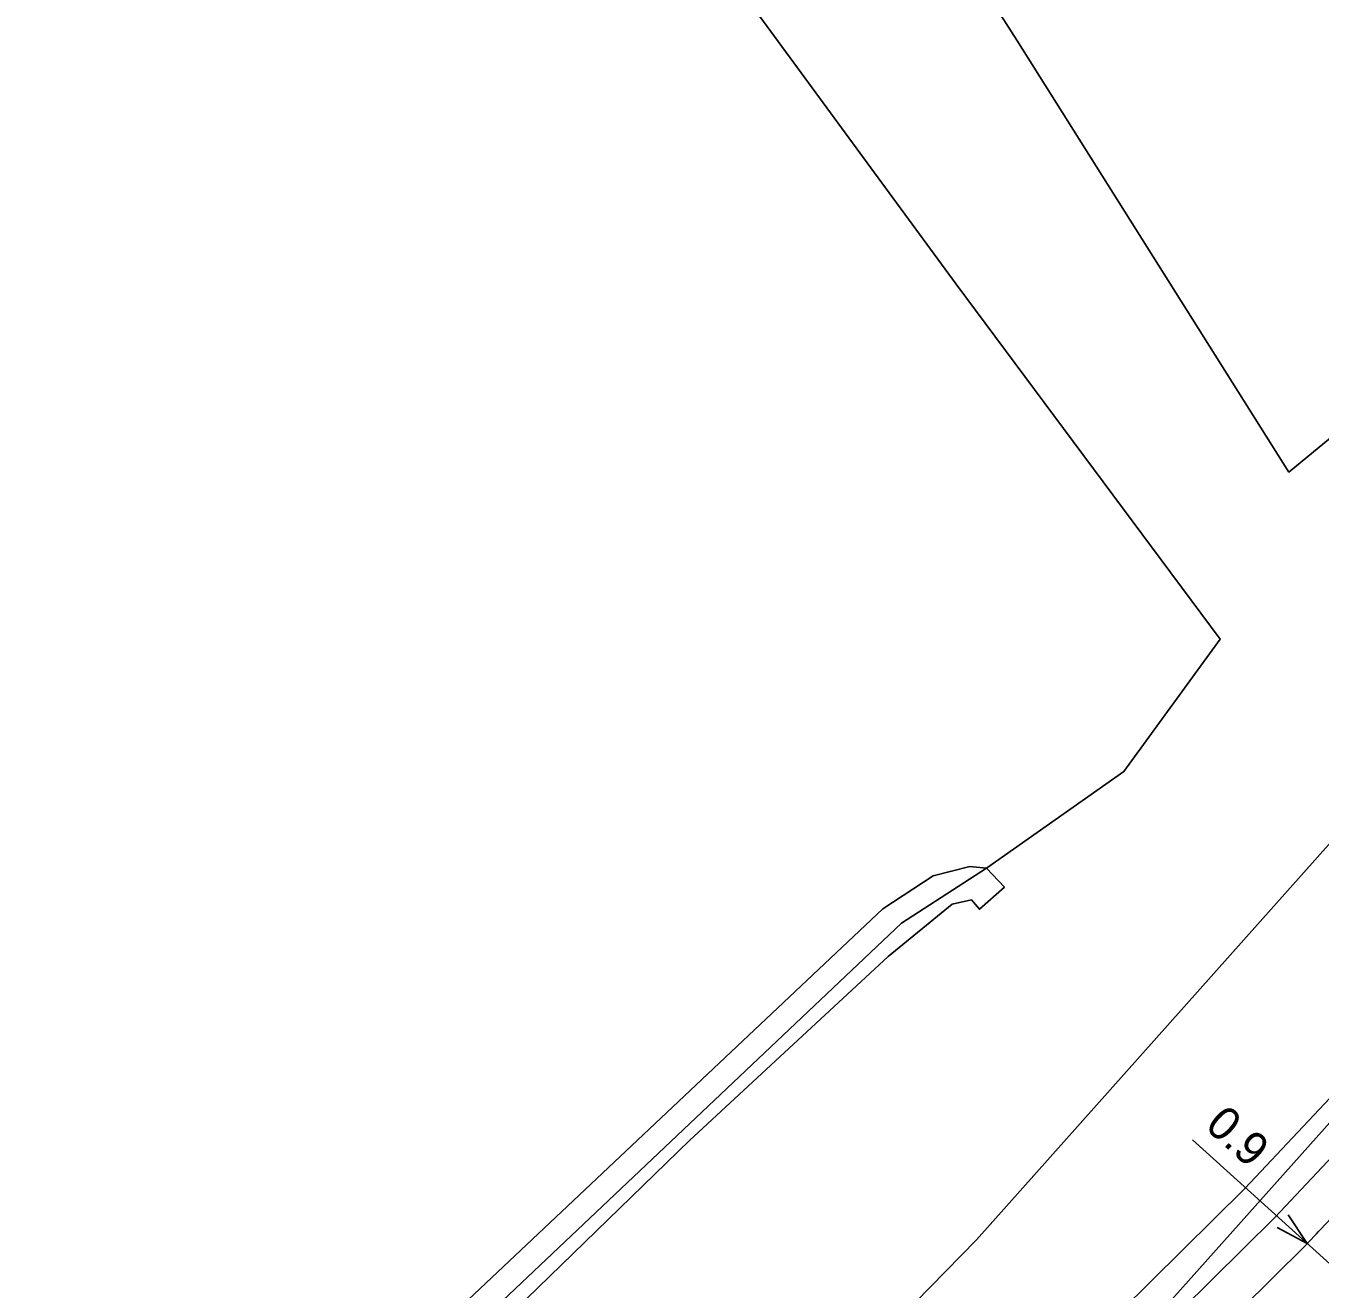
# Model space of a CAD drawing. Extents: x -836739 to -834468, y -1071001 to -1070126.
# Drawn here: x -836503.5 to -836480.21, y -1070291.33 to -1070268.59 of the extents above; entities that cross this region are included whole.
import ezdxf

# ---------------------------------------------------------------- set-up
doc = ezdxf.new("R2010")
doc.units = 0
for name, color, linetype in [('f001_pol_linie', 7, 'Continuous'), ('f006_osa_trasy', 7, 'Continuous'), ('f006_stp_koty', 7, 'Continuous'), ('f309_trubka', 7, 'Continuous')]:
    doc.layers.add(name, color=color, linetype=linetype)

msp = doc.modelspace()

# ---------------------------------------------------------------- linework, layer by layer
at = {"layer": 'f001_pol_linie'}
for points in [[(-836463.13, -1070260.78), (-836466.54, -1070263.19), (-836466.2, -1070265.91), (-836466.63, -1070266.39), (-836466.02, -1070267.34), (-836466.37, -1070268.96), (-836467.68, -1070270.88), (-836477.85, -1070280.85), (-836486.39, -1070290.44)], [(-836490.71, -1070260.96), (-836485.67, -1070268.85), (-836480.77, -1070276.62), (-836476.92, -1070273.45)], [(-836492.75, -1070265.06), (-836486.76, -1070273.24), (-836482.01, -1070279.63), (-836483.74, -1070282.01), (-836486.21, -1070283.75)], [(-836473.79, -1070281.33), (-836483.18, -1070291.85), (-836486.04, -1070295.25), (-836496.69, -1070306.07), (-836498.64, -1070308.92), (-836508.98, -1070315.34), (-836516.87, -1070318.79), (-836525.05, -1070322.08), (-836528.75, -1070323.23)], [(-836538.28, -1070299.17), (-836536.67, -1070302.12), (-836537.27, -1070302.49), (-836535.82, -1070305.08), (-836535.28, -1070304.8), (-836529.27, -1070315.73), (-836524.75, -1070314.46), (-836523.12, -1070313.78), (-836521.89, -1070313.32), (-836519.48, -1070312.36), (-836516.81, -1070310.51), (-836511.44, -1070307.01), (-836506.56, -1070303.42), (-836500.78, -1070297.61), (-836491.56, -1070288.65), (-836487.98, -1070285.34), (-836486.83, -1070284.4), (-836486.48, -1070284.32), (-836486.34, -1070284.49), (-836485.89, -1070284.09), (-836486.21, -1070283.75)], [(-836521.92, -1070312.95), (-836519.9, -1070312.2), (-836512.67, -1070307.44), (-836507.45, -1070303.71), (-836506.51, -1070302.98), (-836501.2, -1070297.48), (-836487.74, -1070284.74), (-836486.21, -1070283.75)], [(-836486.21, -1070283.75), (-836486.51, -1070283.72), (-836487.17, -1070283.89), (-836488.08, -1070284.48), (-836496.59, -1070292.51), (-836502.23, -1070298.08), (-836506.71, -1070302.82)], [(-836486.39, -1070290.44), (-836498.54, -1070302.85), (-836505.49, -1070308.01), (-836514.78, -1070313.23), (-836530.36, -1070319.04), (-836537.03, -1070321.73), (-836555.38, -1070326.29), (-836561.14, -1070327.96), (-836562.04, -1070328.06)]]:
    msp.add_lwpolyline(points, dxfattribs=at)
at = {"layer": 'f006_osa_trasy'}
msp.add_lwpolyline([(-836457.65, -1070271.21), (-836461.44, -1070273.73), (-836465.05, -1070276.12), (-836472.49, -1070282.84), (-836476.33, -1070286.14), (-836480.49, -1070290.56), (-836484.46, -1070294.49), (-836485.91, -1070295.8), (-836486.17, -1070297), (-836486.38, -1070297.88), (-836489.6, -1070301.51), (-836494.07, -1070306.05), (-836498.93, -1070309.99), (-836500.26, -1070310.81)], dxfattribs=at)
at = {"layer": 'f006_stp_koty'}
for points in [[(-836479.537, -1070291.321), (-836482.506, -1070288.641)], [(-836480.784, -1070289.991), (-836480.44, -1070290.505), (-836480.985, -1070290.214)], [(-836480.288, -1070290.337), (-836480.239, -1070290.282)]]:
    msp.add_lwpolyline(points, dxfattribs=at)
at = {"layer": 'f309_trubka'}
for points in [[(-836466.468, -1070259.09), (-836459.302, -1070268.728), (-836458.973, -1070269.389), (-836458.634, -1070270.069), (-836462.269, -1070272.48), (-836465.972, -1070274.932), (-836473.482, -1070281.714), (-836477.368, -1070285.054), (-836481.564, -1070289.512), (-836485.491, -1070293.4), (-836487.006, -1070294.77), (-836495.142, -1070304.988), (-836499.8, -1070308.764), (-836506.642, -1070312.996), (-836515.474, -1070317.594), (-836521.802, -1070319.876), (-836532.34, -1070323.572), (-836539.962, -1070325.81), (-836542.393, -1070326.52), (-836543.113, -1070326.73), (-836550.512, -1070328.89)], [(-836458.661, -1070268.334), (-836457.667, -1070270.328), (-836461.855, -1070273.105), (-836465.511, -1070275.526), (-836472.986, -1070282.277), (-836476.849, -1070285.597), (-836481.027, -1070290.036), (-836484.975, -1070293.945), (-836486.458, -1070295.285), (-836494.606, -1070305.519), (-836499.365, -1070309.377), (-836506.271, -1070313.648), (-836515.172, -1070318.282), (-836521.551, -1070320.583), (-836532.11, -1070324.286), (-836539.751, -1070326.53), (-836542.183, -1070327.24), (-836542.903, -1070327.45), (-836550.286, -1070329.605)], [(-836500.259, -1070310.812), (-836498.93, -1070309.99), (-836494.07, -1070306.05), (-836485.91, -1070295.8), (-836484.46, -1070294.49), (-836480.49, -1070290.56), (-836476.33, -1070286.14), (-836472.49, -1070282.84), (-836465.05, -1070276.12), (-836461.44, -1070273.73), (-836458.925, -1070272.058), (-836458.298, -1070271.646), (-836457.635, -1070271.234)]]:
    msp.add_lwpolyline(points, dxfattribs=at)

# ---------------------------------------------------------------- texts
at = {"layer": 'f006_stp_koty'}
msp.add_text('0.9', height=0.6, rotation=317.93, dxfattribs=at).set_placement((-836482.304, -1070288.418))

doc.saveas('drawing.dxf')
